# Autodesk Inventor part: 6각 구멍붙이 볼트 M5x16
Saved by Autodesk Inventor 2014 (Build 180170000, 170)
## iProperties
Created: 2026-10
Part Number: 6각 구멍붙이 볼트 M5x16
Material: 일반
Document SubType Name: Modeling
Designer: dg
Density: 1 g/cm^3
Appearance: 기본값
Author: dg
Author: jhkim
Description: 6각머리 태핑 나사
Creation Date: 2026-09-29
Sending System: Autodesk Inventor 2027
Preprocessor: ST-DEVELOPER v20.1
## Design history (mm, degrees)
node "6각 구멍붙이 볼트 M5x161"
body "Solid1"
node "기준1"
